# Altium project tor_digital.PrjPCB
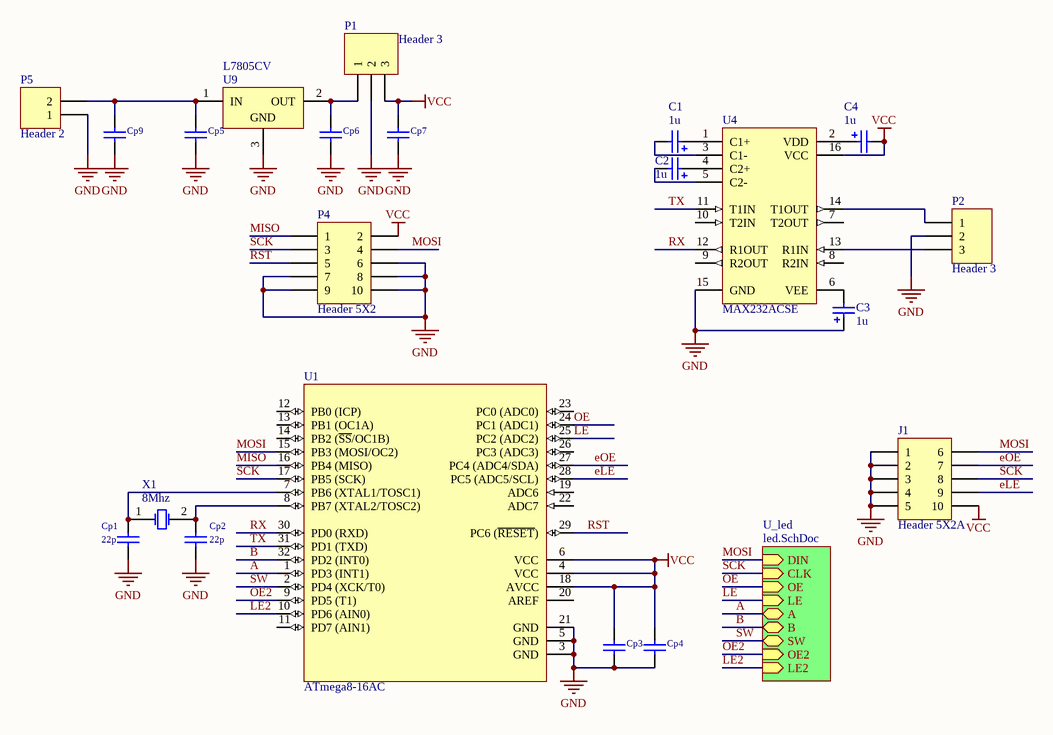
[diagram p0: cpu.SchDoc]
2 sheets, 65 parts. Net scope: hierarchical (ports join the sheet entries above them; power ports are global).
Board file: digital.PcbDoc
Sheets:
  cpu.SchDoc
    U_led = led.SchDoc

## Sheet cpu.SchDoc
size A

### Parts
C1  value 1u  [C1206]  (hidden comment: Cap Pol2)
C2  value 1u  [C1206]  (hidden comment: Cap Pol2)
C3  value 1u  [C1206]  (hidden comment: Cap Pol2)
C4  value 1u  [C1206]  (hidden comment: Cap Pol2)
Cp1  value 22p  [C1206]  (hidden comment: Cap)
Cp2  value 22p  [C1206]  (hidden comment: Cap)
Cp3  Cap  [C1206]  (value not drawn)
Cp4  Cap  [C1206]  (value not drawn)
Cp5  Cap  [C1206]  (value not drawn)
Cp6  Cap  [C1206]  (value not drawn)
Cp7  Cap  [C1206]  (value not drawn)
Cp9  Cap  [C1206]  (value not drawn)
J1  Header 5X2A  [HDR2X5_CEN]
P1  Header 3  [HDR1X3]
P2  Header 3  [HDR1X3]
P4  Header 5X2  [HDR2X5]
P5  Header 2  [HDR1X2]
U1  ATmega8-16AC  [32A_L]
U4  MAX232ACSE  [NSO16_N]
U9  L7805CV  [TO220ABN]
X1  8Mhz  [C1206]

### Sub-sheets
U_led = led.SchDoc: DIN (in), CLK (in), OE (in), LE (in), A (bidir), B (bidir), SW (bidir), OE2 (in), LE2 (in)

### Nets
GND: C3.1 Cp1.2 Cp2.2 Cp3.2 Cp4.2 Cp5.2 Cp6.2 Cp7.2 Cp9.2 J1.1 J1.2 J1.3 J1.4 J1.5 P1.2 P2.2 P4.6 P4.7 P4.8 P4.9 P4.10 P5.1 U1.3(GND) U1.5(GND) U1.21(GND) U4.15(GND) U9.3(GND)
VCC: C4.2 Cp3.1 Cp4.1 Cp7.1 J1.10 P1.3 P4.2 U1.4(VCC) U1.6(VCC) U1.18(AVCC) U4.16(VCC)
A: U1.1(PD3_(INT1)) ; sheet U_led/A
B: U1.32(PD2_(INT0)) ; sheet U_led/B
eLE: J1.9 U1.28(PC5_(ADC5/SCL))
eOE: J1.7 U1.27(PC4_(ADC4/SDA))
LE: U1.25(PC2_(ADC2)) ; sheet U_led/LE
LE2: U1.10(PD6_(AIN0)) ; sheet U_led/LE2
MISO: P4.1 U1.16(PB4_(MISO))
MOSI: J1.6 P4.4 U1.15(PB3_(MOSI/OC2)) ; sheet U_led/DIN  [project net DIN]
OE: U1.24(PC1_(ADC1)) ; sheet U_led/OE
OE2: U1.9(PD5_(T1)) ; sheet U_led/OE2
RST: P4.5 U1.29(PC6_(~{RESET}))
RX: U1.30(PD0_(RXD)) U4.12(R1OUT)
SCK: J1.8 P4.3 U1.17(PB5_(SCK)) ; sheet U_led/CLK  [project net CLK]
SW: U1.2(PD4_(XCK/T0)) ; sheet U_led/SW
TX: U1.31(PD1_(TXD)) U4.11(T1IN)
NetC1_1: C1.1 U4.1(C1+)
NetC1_2: C1.2 U4.3(C1-)
NetC2_1: C2.1 U4.4(C2+)
NetC2_2: C2.2 U4.5(C2-)
NetC3_2: C3.2 U4.6(VEE)
NetC4_1: C4.1 U4.2(VDD)
NetCp1_1: Cp1.1 U1.7(PB6_(XTAL1/TOSC1)) X1.1(OSC1)
NetCp2_1: Cp2.1 U1.8(PB7_(XTAL2/TOSC2)) X1.2(OSC2)
NetCp5_1: Cp5.1 Cp9.1 P5.2 U9.1(IN)
NetCp6_1: Cp6.1 P1.1 U9.2(OUT)
NetP2_1: P2.1 U4.14(T1OUT)
NetP2_3: P2.3 U4.13(R1IN)

Not connected (* = marked no-connect by the designer): U1 11(PD7_(AIN1)) 12(PB0_(ICP)) 13(PB1_(OC1A)) 14(PB2_(~{SS}/OC1B)) 19(ADC6) 20(AREF) 22(ADC7) 23(PC0_(ADC0)) 26(PC3_(ADC3)); U4 7(T2OUT) 8(R2IN) 9(R2OUT) 10(T2IN)

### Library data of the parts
C1-C4 = Cap Pol2: Polarized Capacitor (Axial)
Cp1-Cp7 Cp9 = Cap: Capacitor
J1 = Header 5X2A: Header, 5-Pin, Dual row
P1 P2 = Header 3: Header, 3-Pin
P4 = Header 5X2: Header, 5-Pin, Dual row
P5 = Header 2: Header, 2-Pin
U1 = ATmega8-16AC: 8-Bit AVR Microcontroller with 8K Bytes of In-System Programmable Flash Memory
U4 = MAX232ACSE: +5V Powered, Multi-Channel RS-232 Driver/Receiver
U9 = L7805CV: Positive Voltage Regulator; Note: Tab is connected to pin 3 (GND).
X1 = XTAL: Crystal Oscillator

## Sheet led.SchDoc
size A
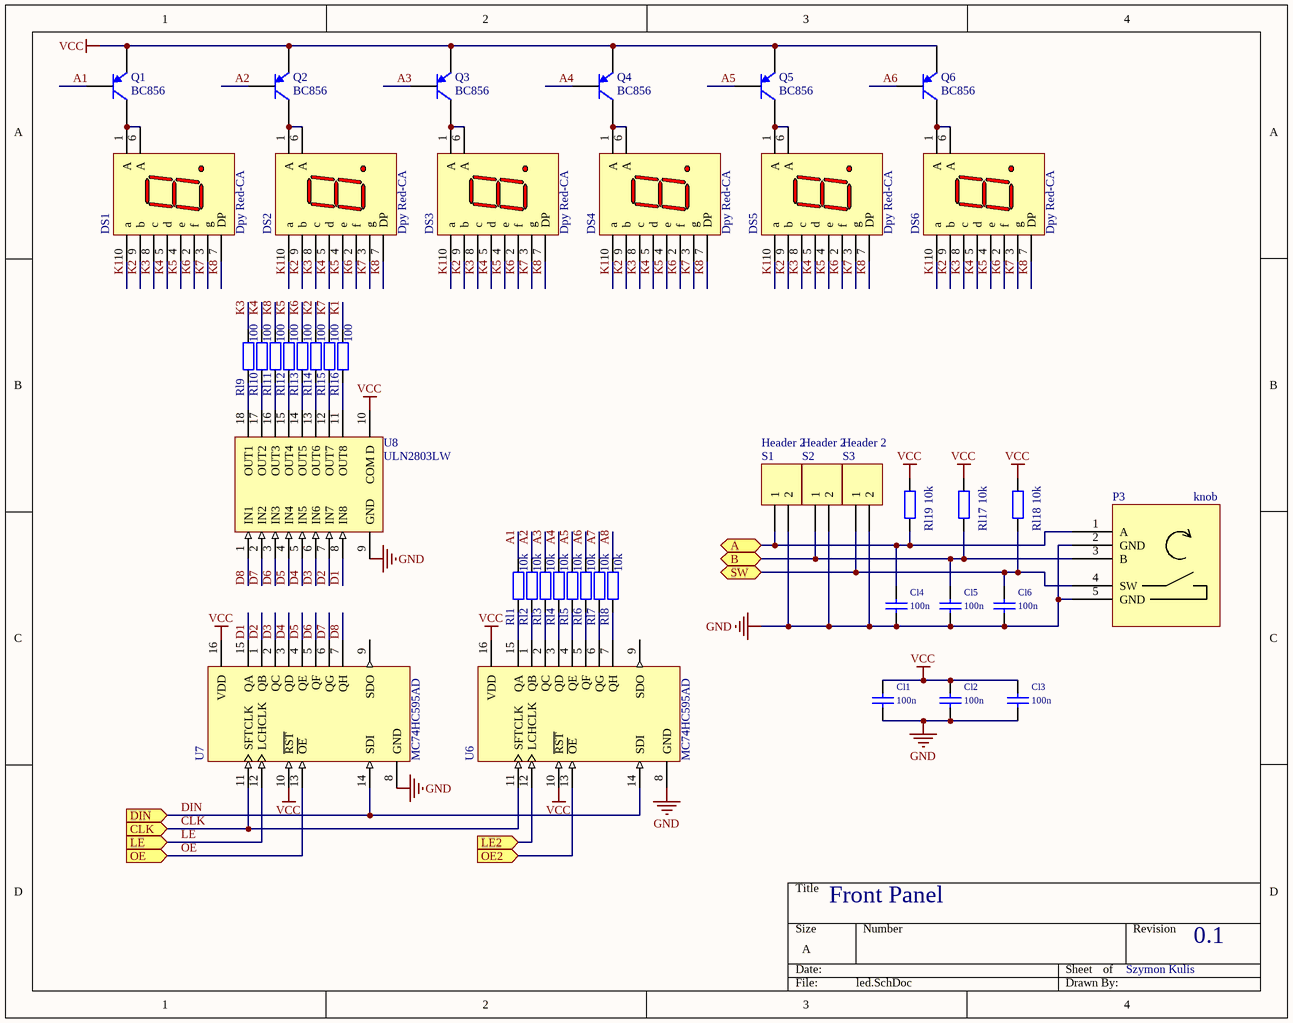
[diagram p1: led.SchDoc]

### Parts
Cl1  value 100n  [C0805]  (hidden comment: Cap)
Cl2  value 100n  [C0805]  (hidden comment: Cap)
Cl3  value 100n  [C0805]  (hidden comment: Cap)
Cl4  value 100n  [C0805]  (hidden comment: Cap)
Cl5  value 100n  [C0805]  (hidden comment: Cap)
Cl6  value 100n  [C0805]  (hidden comment: Cap)
DS1  Dpy Red-CA  [DIP10_7seg]
DS2  Dpy Red-CA  [DIP10_7seg]
DS3  Dpy Red-CA  [DIP10_7seg]
DS4  Dpy Red-CA  [DIP10_7seg]
DS5  Dpy Red-CA  [DIP10_7seg]
DS6  Dpy Red-CA  [DIP10_7seg]
P3  knob
Q1  BC856  [SOT-23B]
Q2  BC856  [SOT-23B]
Q3  BC856  [SOT-23B]
Q4  BC856  [SOT-23B]
Q5  BC856  [SOT-23B]
Q6  BC856  [SOT-23B]
Rl1  value 10k  [C0805]  (hidden comment: Res2)
Rl2  value 10k  [C0805]  (hidden comment: Res2)
Rl3  value 10k  [C0805]  (hidden comment: Res2)
Rl4  value 10k  [C0805]  (hidden comment: Res2)
Rl5  value 10k  [C0805]  (hidden comment: Res2)
Rl6  value 10k  [C0805]  (hidden comment: Res2)
Rl7  value 10k  [C0805]  (hidden comment: Res2)
Rl8  value 10k  [C0805]  (hidden comment: Res2)
Rl9  value 100  [C0805]  (hidden comment: Res2)
Rl10  value 100  [C0805]  (hidden comment: Res2)
Rl11  value 100  [C0805]  (hidden comment: Res2)
Rl12  value 100  [C0805]  (hidden comment: Res2)
Rl13  value 100  [C0805]  (hidden comment: Res2)
Rl14  value 100  [C0805]  (hidden comment: Res2)
Rl15  value 100  [C0805]  (hidden comment: Res2)
Rl16  value 100  [C0805]  (hidden comment: Res2)
Rl17  value 10k  [C0805]  (hidden comment: Res2)
Rl18  value 10k  [C0805]  (hidden comment: Res2)
Rl19  value 10k  [C0805]  (hidden comment: Res2)
S1  Header 2  [HDR1X2]
S2  Header 2  [HDR1X2]
S3  Header 2  [HDR1X2]
U6  MC74HC595AD  [751B-05_N]
U7  MC74HC595AD  [751B-05_N]
U8  ULN2803LW  [LW18_L]

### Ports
A (bidir), B (bidir), CLK (in), DIN (in), LE2 (in), LE (in), OE2 (in), OE (in), SW (bidir)

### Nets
GND: Cl1.2 Cl2.2 Cl3.2 Cl4.2 Cl5.2 Cl6.2 P3.2(GND) P3.5(GND) S1.2 S2.2 S3.2 U6.8(GND) U7.8(GND) U8.9(GND)
VCC: Cl1.1 Cl2.1 Cl3.1 Q1.3(E) Q2.3(E) Q3.3(E) Q4.3(E) Q5.3(E) Q6.3(E) Rl17.2 Rl18.2 Rl19.2 U6.10(~{RST}) U6.16(VDD) U7.10(~{RST}) U7.16(VDD) U8.10(COM_D)
A: Cl4.1 P3.1(A) Rl19.1 S1.1 ; port A
A1: Q1.2(B) Rl1.2
A2: Q2.2(B) Rl2.2
A3: Q3.2(B) Rl3.2
A4: Q4.2(B) Rl4.2
A5: Q5.2(B) Rl5.2
A6: Q6.2(B) Rl6.2
A7: Rl7.2
A8: Rl8.2
B: Cl5.1 P3.3(B) Rl17.1 S2.1 ; port B
CLK: U6.11(SFTCLK) U7.11(SFTCLK) ; port CLK
D1: U7.15(QA) U8.8(IN8)
D2: U7.1(QB) U8.7(IN7)
D3: U7.2(QC) U8.6(IN6)
D4: U7.3(QD) U8.5(IN5)
D5: U7.4(QE) U8.4(IN4)
D6: U7.5(QF) U8.3(IN3)
D7: U7.6(QG) U8.2(IN2)
D8: U7.7(QH) U8.1(IN1)
DIN: U6.14(SDI) U7.14(SDI) ; port DIN
K1: DS1.10(a) DS2.10(a) DS3.10(a) DS4.10(a) DS5.10(a) DS6.10(a) Rl16.2
K2: DS1.9(b) DS2.9(b) DS3.9(b) DS4.9(b) DS5.9(b) DS6.9(b) Rl14.2
K3: DS1.8(c) DS2.8(c) DS3.8(c) DS4.8(c) DS5.8(c) DS6.8(c) Rl9.2
K4: DS1.5(d) DS2.5(d) DS3.5(d) DS4.5(d) DS5.5(d) DS6.5(d) Rl10.2
K5: DS1.4(e) DS2.4(e) DS3.4(e) DS4.4(e) DS5.4(e) DS6.4(e) Rl12.2
K6: DS1.2(f) DS2.2(f) DS3.2(f) DS4.2(f) DS5.2(f) DS6.2(f) Rl13.2
K7: DS1.3(g) DS2.3(g) DS3.3(g) DS4.3(g) DS5.3(g) DS6.3(g) Rl15.2
K8: DS1.7(DP) DS2.7(DP) DS3.7(DP) DS4.7(DP) DS5.7(DP) DS6.7(DP) Rl11.2
LE: U7.12(LCHCLK) ; port LE
LE2: U6.12(LCHCLK) ; port LE2
OE: U7.13(~{OE}) ; port OE
OE2: U6.13(~{OE}) ; port OE2
SW: Cl6.1 P3.4(SW) Rl18.1 S3.1 ; port SW
NetDS1_1: DS1.1(A) DS1.6(A) Q1.1(C)
NetDS2_1: DS2.1(A) DS2.6(A) Q2.1(C)
NetDS3_1: DS3.1(A) DS3.6(A) Q3.1(C)
NetDS4_1: DS4.1(A) DS4.6(A) Q4.1(C)
NetDS5_1: DS5.1(A) DS5.6(A) Q5.1(C)
NetDS6_1: DS6.1(A) DS6.6(A) Q6.1(C)
NetRl1_1: Rl1.1 U6.15(QA)
NetRl2_1: Rl2.1 U6.1(QB)
NetRl3_1: Rl3.1 U6.2(QC)
NetRl4_1: Rl4.1 U6.3(QD)
NetRl5_1: Rl5.1 U6.4(QE)
NetRl6_1: Rl6.1 U6.5(QF)
NetRl7_1: Rl7.1 U6.6(QG)
NetRl8_1: Rl8.1 U6.7(QH)
NetRl9_1: Rl9.1 U8.18(OUT1)
NetRl10_1: Rl10.1 U8.17(OUT2)
NetRl11_1: Rl11.1 U8.16(OUT3)
NetRl12_1: Rl12.1 U8.15(OUT4)
NetRl13_1: Rl13.1 U8.14(OUT5)
NetRl14_1: Rl14.1 U8.13(OUT6)
NetRl15_1: Rl15.1 U8.12(OUT7)
NetRl16_1: Rl16.1 U8.11(OUT8)

Not connected (* = marked no-connect by the designer): U6 9(SDO); U7 9(SDO)

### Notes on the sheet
- Front Panel
- Szymon Kulis
- 0.1

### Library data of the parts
Cl1-Cl6 = Cap: Capacitor
DS1-DS6 = Dpy Red-CA: 7.62 mm Black Surface HER 7-Segment Display: CA, RH DP; MinimumIntensity: 360 ucd; Note: IF = 5 mA; Colour: High Efficiency Red (HER); Note: Pins 1 and 6 are redundant Anodes.
Q1-Q6 = PNP: PNP Bipolar Transistor
Rl1-Rl19 = Res2: Resistor
S1-S3 = Header 2: Header, 2-Pin
U6 U7 = MC74HC595AD: 8-Bit Serial-Input/Serial or Prallel-Output Shift Register with Latched 3-State Outputs
U8 = ULN2803LW: High-Voltage, High-Current Darlington Array

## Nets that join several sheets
GND: cpu (27 pins), led (14 pins)
VCC: cpu (11 pins), led (17 pins)
A: cpu (U1.1), led (Cl4.1 P3.1 Rl19.1 S1.1)
B: cpu (U1.32), led (Cl5.1 P3.3 Rl17.1 S2.1)
CLK: cpu (J1.8 P4.3 U1.17), led (U6.11 U7.11)
DIN: cpu (J1.6 P4.4 U1.15), led (U6.14 U7.14)
LE: cpu (U1.25), led (U7.12)
LE2: cpu (U1.10), led (U6.12)
OE: cpu (U1.24), led (U7.13)
OE2: cpu (U1.9), led (U6.13)
SW: cpu (U1.2), led (Cl6.1 P3.4 Rl18.1 S3.1)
